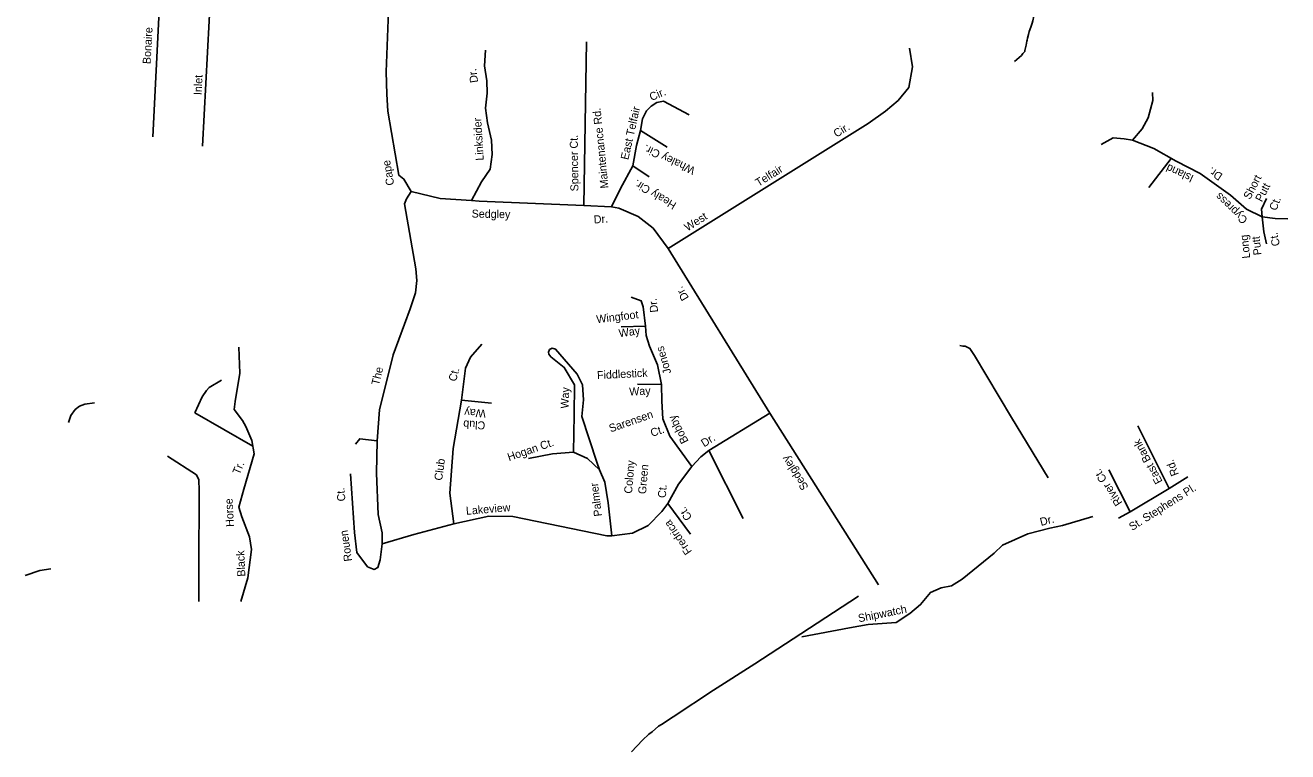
# Model space of a CAD drawing. Extents: x 2308163 to 2335412, y -96774 to 125428.
# Drawn here: x 2322154.7 to 2322235.6, y 82484.8 to 82531.3 of the extents above; entities that cross this region are included whole.
import ezdxf

# ---------------------------------------------------------------- set-up
doc = ezdxf.new("R2010")
doc.units = 0
doc.layers.add('Old_Level_10', color=7, linetype='Continuous')
doc.layers.add('Old_Level_35', color=7, linetype='Continuous')

msp = doc.modelspace()

# ---------------------------------------------------------------- linework, layer by layer
at = {"layer": 'Old_Level_35'}
for points in [[(2322166.051, 82523.577), (2322166.57, 82533.639), (2322166.862, 82537.123), (2322166.872, 82540.731), (2322167.172, 82544.444), (2322166.894, 82548.004), (2322166.917, 82550.352), (2322167.502, 82552.336), (2322167.735, 82554.104), (2322167.766, 82556.68)], [(2322162.862, 82524.179), (2322164.333, 82553.534), (2322164.021, 82556.122)], [(2322179.416, 82520.668), (2322178.952, 82521.469), (2322178.633, 82521.71), (2322177.923, 82525.825), (2322177.862, 82526.907), (2322177.814, 82528.348), (2322177.929, 82531.682), (2322177.893, 82532.534), (2322177.769, 82534.633), (2322177.633, 82536.405), (2322177.699, 82537.352), (2322178.058, 82538.288), (2322178.813, 82539.277), (2322179.37, 82540.24), (2322179.874, 82541.564), (2322180.481, 82543.965), (2322181.09, 82546.431), (2322181.92, 82549.609), (2322182.615, 82552.662), (2322182.851, 82554.384)], [(2322218.877, 82530.36), (2322218.914, 82530.492), (2322218.967, 82530.725), (2322219.017, 82530.928), (2322219.118, 82531.205), (2322219.204, 82531.47), (2322219.254, 82531.611), (2322219.272, 82531.719), (2322219.289, 82531.811), (2322219.276, 82531.952), (2322219.295, 82532.108), (2322219.233, 82532.72), (2322219.133, 82533.755), (2322219.005, 82534.915), (2322218.951, 82535.307), (2322218.949, 82535.822), (2322218.933, 82536.431), (2322218.972, 82537.446), (2322219.025, 82539.04), (2322219.127, 82541.303), (2322219.188, 82542.899)], [(2322190.474, 82519.783), (2322190.646, 82530.269)], [(2322218.066, 82529.012), (2322218.512, 82529.391), (2322218.609, 82529.514), (2322218.688, 82529.607), (2322218.736, 82529.651), (2322218.738, 82529.715), (2322218.811, 82530.056), (2322218.861, 82530.305), (2322218.877, 82530.36)], [(2322184.176, 82529.733), (2322184.108, 82528.72), (2322184.271, 82527.766), (2322184.277, 82526.98), (2322184.178, 82526.002), (2322184.31, 82525.081), (2322184.566, 82523.959), (2322184.6, 82523.042), (2322184.469, 82522.097), (2322183.917, 82521.298), (2322183.286, 82520.096)], [(2322195.88, 82517.011), (2322208.699, 82525.032), (2322209.807, 82525.812), (2322210.617, 82526.504), (2322211.3, 82527.331), (2322211.543, 82528.664), (2322211.354, 82529.849)], [(2322225.625, 82523.972), (2322226.247, 82524.68), (2322226.636, 82525.395), (2322226.94, 82526.512), (2322226.924, 82527.01)], [(2322192.239, 82519.689), (2322192.836, 82520.866), (2322193.607, 82522.312), (2322193.848, 82523.613), (2322194.111, 82524.586), (2322194.235, 82525.334), (2322194.482, 82525.849), (2322194.786, 82526.133), (2322195.155, 82526.382), (2322195.584, 82526.466), (2322197.224, 82525.591)], [(2322194.111, 82524.586), (2322195.809, 82523.513)], [(2322223.624, 82523.676), (2322224.402, 82524.113), (2322225.097, 82524.056), (2322225.625, 82523.972), (2322227, 82523.427), (2322228.431, 82522.615), (2322229.964, 82521.833), (2322231.906, 82520.44), (2322232.937, 82519.542), (2322233.948, 82519.043), (2322233.899, 82519.542), (2322234.221, 82520.227)], [(2322226.681, 82520.918), (2322228.12, 82522.792)], [(2322193.607, 82522.312), (2322194.664, 82521.621)], [(2322179.416, 82520.668), (2322179.105, 82520.194), (2322178.995, 82519.871), (2322179.704, 82515.723), (2322179.776, 82514.968), (2322179.683, 82514.186), (2322179.353, 82513.15), (2322178.269, 82510.209), (2322177.394, 82506.679), (2322177.227, 82504.688), (2322177.189, 82502.628), (2322177.294, 82499.974), (2322177.548, 82498.787), (2322177.557, 82498.099), (2322177.422, 82497.057), (2322177.275, 82496.571), (2322177.041, 82496.448), (2322176.622, 82496.626), (2322175.932, 82497.533), (2322175.78, 82498.815), (2322175.517, 82502.587)], [(2322197.396, 82503.037), (2322197.974, 82503.672), (2322198.48, 82504.08), (2322202.393, 82506.465), (2322195.88, 82517.011), (2322194.91, 82518.321), (2322193.953, 82519.074), (2322192.727, 82519.607), (2322192.239, 82519.689), (2322190.474, 82519.783), (2322183.776, 82520.046), (2322183.286, 82520.096), (2322181.261, 82520.231), (2322179.416, 82520.668)], [(2322233.948, 82519.043), (2322234.048, 82518.078), (2322234.22, 82517.31)], [(2322233.948, 82519.043), (2322234.774, 82518.948), (2322235.58, 82518.914)], [(2322177.557, 82498.099), (2322179.574, 82498.684), (2322182.153, 82499.381), (2322184.396, 82499.859), (2322185.935, 82499.839), (2322190.39, 82498.926), (2322191.951, 82498.611), (2322192.278, 82498.599), (2322193.594, 82498.783), (2322194.594, 82499.272), (2322195.476, 82500.158), (2322195.853, 82500.669), (2322196.539, 82501.921), (2322197.396, 82503.037), (2322195.989, 82504.984), (2322195.537, 82506.112), (2322195.477, 82507.227), (2322195.449, 82508.308), (2322195.197, 82509.56), (2322194.682, 82510.756), (2322194.477, 82511.45), (2322194.431, 82512.041), (2322194.278, 82513.29), (2322194.16, 82513.654), (2322193.513, 82513.905)], [(2322194.431, 82512.041), (2322192.858, 82511.997)], [(2322168.499, 82494.389), (2322168.954, 82495.904), (2322169.189, 82497.729), (2322169.045, 82498.536), (2322168.573, 82499.812), (2322168.366, 82500.449), (2322168.692, 82501.584), (2322169.343, 82503.852), (2322169.201, 82504.716), (2322168.817, 82505.617), (2322168.615, 82505.996), (2322168.066, 82506.703), (2322168.141, 82507.216), (2322168.433, 82509.038), (2322168.376, 82510.701)], [(2322182.153, 82499.381), (2322181.899, 82501.333), (2322182.097, 82504.206), (2322182.629, 82507.297), (2322182.896, 82509.349), (2322183.215, 82510.058), (2322183.932, 82510.884)], [(2322189.817, 82503.973), (2322189.867, 82506.36), (2322189.868, 82508.291), (2322189.218, 82509.393), (2322188.358, 82510.077), (2322188.232, 82510.245), (2322188.204, 82510.377), (2322188.275, 82510.538), (2322188.442, 82510.631), (2322188.669, 82510.557), (2322190.055, 82508.971), (2322190.391, 82508.273), (2322190.457, 82507.321), (2322190.354, 82506.245), (2322191.302, 82503.332), (2322191.481, 82502.835)], [(2322220.22, 82502.322), (2322217.889, 82506.192), (2322215.5, 82510.157), (2322215.213, 82510.619), (2322215.09, 82510.683), (2322214.92, 82510.749), (2322214.764, 82510.768), (2322214.561, 82510.806)], [(2322165.551, 82506.494), (2322166.027, 82507.503), (2322166.302, 82507.911), (2322166.466, 82508.114), (2322167.254, 82508.58)], [(2322195.449, 82508.308), (2322193.91, 82508.328)], [(2322157.463, 82505.86), (2322157.609, 82506.311), (2322157.887, 82506.7), (2322158.169, 82506.906), (2322158.508, 82507.051), (2322159.118, 82507.128)], [(2322165.551, 82506.494), (2322169.26, 82504.354)], [(2322182.629, 82507.297), (2322184.554, 82507.099)], [(2322202.393, 82506.465), (2322209.348, 82495.467)], [(2322225.969, 82505.653), (2322227.987, 82501.638), (2322229.174, 82502.393)], [(2322177.227, 82504.688), (2322176.118, 82504.825), (2322175.844, 82504.474)], [(2322198.48, 82504.08), (2322200.687, 82499.717)], [(2322163.795, 82503.715), (2322165.657, 82502.519), (2322165.805, 82502.195), (2322165.833, 82501.502), (2322165.817, 82496.506), (2322165.814, 82494.397)], [(2322192.278, 82498.599), (2322192.03, 82500.722), (2322191.814, 82502.038), (2322191.481, 82502.835), (2322190.72, 82503.549), (2322189.817, 82503.973), (2322188.47, 82503.855), (2322186.921, 82503.549)], [(2322225.48, 82500.133), (2322224.113, 82502.833)], [(2322227.987, 82501.638), (2322225.48, 82500.133), (2322224.736, 82499.728)], [(2322195.853, 82500.669), (2322197.312, 82498.72)], [(2322204.449, 82492.139), (2322207.494, 82492.697), (2322208.696, 82492.921), (2322210.492, 82493.058), (2322211.374, 82493.624), (2322212.058, 82494.198), (2322212.681, 82494.972), (2322213.369, 82495.28), (2322214.036, 82495.389), (2322214.715, 82495.83), (2322216.762, 82497.483), (2322217.311, 82497.995), (2322218.929, 82498.735), (2322220.334, 82499.084), (2322221.137, 82499.255), (2322223.081, 82499.851)], [(2322154.685, 82496.062), (2322155.611, 82496.387), (2322156.326, 82496.481)], [(2322208.085, 82494.734), (2322204.384, 82492.318), (2322201.429, 82490.404), (2322198.793, 82488.703), (2322196.204, 82486.999), (2322195.443, 82486.501), (2322195.267, 82486.395), (2322194.853, 82486.047), (2322194.644, 82485.895), (2322194.228, 82485.498), (2322193.532, 82484.764)]]:
    msp.add_lwpolyline(points, dxfattribs=at)

# ---------------------------------------------------------------- texts
at = {"layer": 'Old_Level_10'}
for s, height, rotation, p in [('Bonaire', 0.5126, 86.85287, (2322162.715, 82528.828)), ('Dr.', 0.5126, 98.31149, (2322183.706, 82527.675)), ('Inlet', 0.5126, 87.81616, (2322165.994, 82526.843)), ('Cir.', 0.5126, 22.8854, (2322194.808, 82526.465)), ('Maintenance Rd.', 0.51263, 95.70483, (2322192.06, 82520.894)), ('East Telfair ', 0.51263, 77.27677, (2322193.323, 82522.669)), ('Linksider', 0.5126, 93.46845, (2322184.064, 82522.668)), ('Cir.', 0.5126, 31.76923, (2322206.668, 82524.118)), ('Spencer Ct.', 0.51263, 90.73245, (2322190.131, 82520.683)), ('Whaley Cir.', 0.51263, 154.835, (2322197.659, 82522.19)), ('Cape', 0.5126, 99.96283, (2322178.334, 82521.104)), ('Telfair', 0.5126, 31.80691, (2322201.667, 82520.969)), (' Island ', 0.5126, 155.20343, (2322229.768, 82521.608)), ('Dr.', 0.5126, 146.86381, (2322231.45, 82521.765)), ('Healy Cir.', 0.5126, 149.12092, (2322196.457, 82519.923)), ('Short', 0.5126, 62.50556, (2322233.16, 82520.119)), ('Putt', 0.5126, 62.50556, (2322233.918, 82519.965)), ('Cypress', 0.5126, 136.19916, (2322233.053, 82518.901)), ('Sedgley', 0.5126, 358.97939, (2322183.285, 82519.002)), ('Ct.', 0.5126, 68.66812, (2322234.843, 82519.404)), ('Dr.', 0.5126, 3.77205, (2322191.128, 82518.619)), ('West', 0.5126, 32.36433, (2322197.117, 82518.104)), ('Long', 0.5126, 95.97678, (2322233.177, 82516.406)), ('Putt', 0.5126, 95.97678, (2322233.903, 82516.614)), ('Ct.', 0.5126, 101.76918, (2322235.086, 82517.226)), ('Dr.', 0.5126, 121.02009, (2322197.224, 82513.861)), ('Dr.', 0.5126, 96.5311, (2322195.24, 82512.945)), ('Wingfoot ', 0.5126, 6.88756, (2322191.31, 82512.229)), ('Way', 0.5126, 8.30907, (2322192.752, 82511.325)), ('Jones', 0.5126, 106.32219, (2322196.083, 82509.05)), ('The ', 0.5126, 76.32698, (2322177.35, 82508.215)), ('Ct.', 0.5126, 75.06851, (2322182.284, 82508.46)), ('Fiddlestick', 0.51263, 2.83826, (2322191.335, 82508.643)), ('Way', 0.5126, 87.71185, (2322189.494, 82506.752)), ('Way', 0.5126, 2.83826, (2322193.395, 82507.59)), ('Way', 0.5126, 176.69665, (2322184.207, 82506.686)), ('Sarensen', 0.5126, 19.22892, (2322192.193, 82505.225)), ('Club', 0.5126, 176.69665, (2322184.174, 82505.924)), ('Bobby', 0.5126, 117.11451, (2322197.199, 82504.666)), ('Ct.', 0.5126, 19.22892, (2322194.849, 82504.938)), ('Dr.', 0.5126, 32.30181, (2322198.187, 82504.27)), ('Hogan Ct.', 0.5126, 19.00328, (2322185.683, 82503.384)), ('East Bank', 0.5126, 118.32588, (2322227.575, 82502.091)), ('Club ', 0.5126, 82.31385, (2322181.394, 82502.121)), ('Colony', 0.5126, 85.32775, (2322193.561, 82501.293)), ('Sedgley', 0.5126, 122.91116, (2322204.892, 82501.732)), ('Rd.', 0.5126, 110.76451, (2322228.609, 82502.546)), ('Tr.', 0.5126, 66.88351, (2322168.412, 82502.483)), ('Green ', 0.5126, 85.32775, (2322194.458, 82501.263)), ('River Ct.', 0.5126, 123.40587, (2322225.005, 82500.725)), ('Ct.', 0.5126, 94.67328, (2322175.203, 82500.832)), ('Palmer', 0.5126, 97.01727, (2322191.643, 82499.875)), ('Ct.', 0.5126, 85.32775, (2322195.724, 82501.014)), ('St. Stephens Pl.', 0.51263, 32.47615, (2322225.61, 82498.91)), ('Horse', 0.5126, 92.96596, (2322168.062, 82499.189)), ('Lakeview', 0.5126, 4.75025, (2322182.944, 82499.947)), ('Ct.', 0.5126, 124.48233, (2322197.439, 82499.794)), ('Fredrica', 0.5126, 124.48233, (2322197.426, 82497.602)), ('Dr.', 0.5126, 14.48431, (2322219.773, 82499.234)), ('Rouen', 0.5126, 98.32171, (2322175.628, 82496.998)), ('Black', 0.5126, 92.66996, (2322168.791, 82495.998)), ('Shipwatch', 0.5126, 11.39025, (2322208.103, 82493.056))]:
    msp.add_text(s, height=height, rotation=rotation, dxfattribs=at).set_placement(p)

doc.saveas('drawing.dxf')
